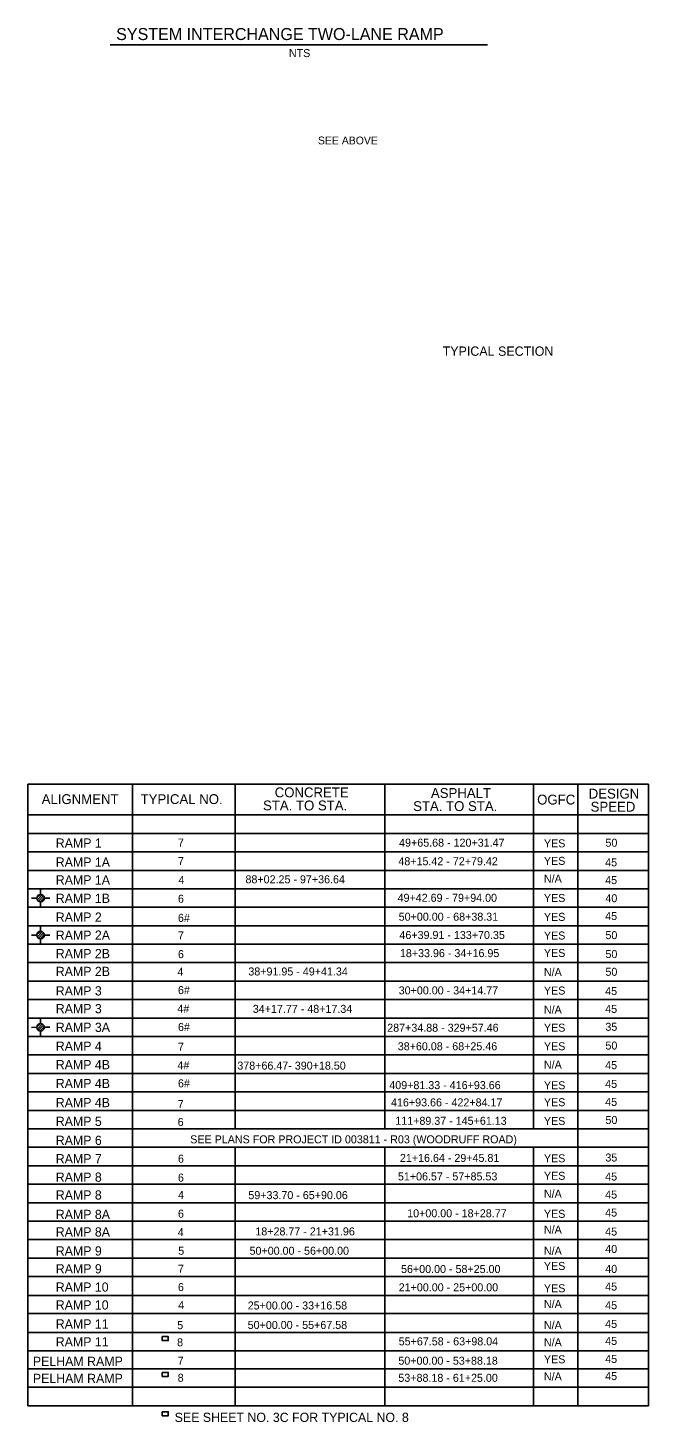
# Model space of a CAD drawing. Extents: x 4649 to 5578, y 4853 to 5383.
# Drawn here: x 5252.3 to 5345.4, y 4852.5 to 5061.7 of the extents above; entities that cross this region are included whole.
import ezdxf

# ---------------------------------------------------------------- set-up
doc = ezdxf.new("R2010")
doc.units = 0
for name, color, linetype in [('Level 1', 7, 'Continuous'), ('Level 3', 7, 'Continuous'), ('RD_EX_SU_Pole', 7, 'Continuous'), ('RD_Sketch10', 7, 'Continuous'), ('RD_TX_TypSect', 7, 'Continuous'), ('RD_XS_TieSlope', 7, 'Continuous')]:
    doc.layers.add(name, color=color, linetype=linetype)

# ---------------------------------------------------------------- blocks, each defined once
blk = doc.blocks.new('SUE_TFP')
at = {"layer": 'RD_EX_SU_Pole'}
for p, q in [((-2.21, 0.13), (-0.13, 2.21)), ((-1.96, -1.03), (1.03, 1.96)), ((-1.31, -1.79), (1.79, 1.31)), ((-0.3, -2.2), (2.2, 0.3)), ((0, 5.5), (0, 2.22)), ((2.22, 0), (5.53, 0.01)), ((-5.53, -0.01), (-2.22, 0)), ((0, -2.22), (0, -5.5))]:
    blk.add_line(p, q, dxfattribs=at)
blk.add_circle((0, 0), 2.22, dxfattribs=at)

msp = doc.modelspace()

# ---------------------------------------------------------------- linework, layer by layer
at = {"layer": 'Level 1'}
for p, q in [((5252.33, 4948.21), (5345.33, 4948.21)), ((5252.33, 4948.21), (5252.33, 4943.6)), ((5268.02, 4948.21), (5268.02, 4943.6)), ((5283.37, 4948.21), (5283.37, 4943.6)), ((5305.8, 4948.21), (5305.8, 4943.6)), ((5328.08, 4948.21), (5328.08, 4943.6)), ((5334.74, 4948.21), (5334.74, 4943.6)), ((5345.33, 4948.21), (5345.33, 4948.21)), ((5345.33, 4948.21), (5345.33, 4943.6)), ((5252.33, 4943.6), (5345.33, 4943.6)), ((5283.37, 4943.6), (5283.37, 4896.53)), ((5305.8, 4943.6), (5305.8, 4896.53)), ((5328.08, 4943.6), (5328.08, 4896.53)), ((5334.74, 4943.6), (5334.74, 4854.99)), ((5283.37, 4893.76), (5283.37, 4854.99)), ((5305.8, 4893.76), (5305.8, 4854.99)), ((5328.08, 4893.76), (5328.08, 4854.99))]:
    msp.add_line(p, q, dxfattribs=at)
at = {"layer": 'RD_TX_TypSect'}
for p, q in [((5264.65, 5059.12), (5321.2, 5059.12)), ((5252.33, 4943.6), (5252.33, 4854.99)), ((5268.02, 4943.6), (5268.02, 4854.99)), ((5345.33, 4943.6), (5345.33, 4854.99)), ((5252.33, 4940.83), (5345.33, 4940.83)), ((5252.33, 4938.06), (5345.33, 4938.06)), ((5252.33, 4935.29), (5345.33, 4935.29)), ((5252.33, 4932.52), (5345.33, 4932.52)), ((5252.33, 4929.75), (5345.33, 4929.75)), ((5252.33, 4926.99), (5345.33, 4926.99)), ((5252.33, 4924.22), (5345.33, 4924.22)), ((5252.33, 4921.45), (5345.33, 4921.45)), ((5252.33, 4918.68), (5345.33, 4918.68)), ((5252.33, 4915.91), (5345.33, 4915.91)), ((5252.33, 4913.14), (5345.33, 4913.14)), ((5252.33, 4910.37), (5345.33, 4910.37)), ((5252.33, 4907.6), (5345.33, 4907.6)), ((5252.33, 4904.83), (5345.33, 4904.83)), ((5252.33, 4902.06), (5345.33, 4902.06)), ((5252.33, 4899.3), (5345.33, 4899.3)), ((5252.33, 4896.53), (5345.33, 4896.53)), ((5252.33, 4893.76), (5345.33, 4893.76)), ((5252.33, 4890.99), (5345.33, 4890.99)), ((5252.33, 4888.22), (5345.33, 4888.22)), ((5252.33, 4885.45), (5345.33, 4885.45)), ((5252.33, 4882.68), (5345.33, 4882.68)), ((5252.33, 4879.91), (5345.33, 4879.91)), ((5252.33, 4877.14), (5345.33, 4877.14)), ((5252.33, 4874.37), (5345.33, 4874.37)), ((5252.33, 4871.54), (5345.33, 4871.54)), ((5252.33, 4868.84), (5345.33, 4868.84)), ((5252.41, 4865.98), (5345.41, 4865.98)), ((5252.33, 4863.24), (5345.33, 4863.24)), ((5252.33, 4860.53), (5345.33, 4860.53)), ((5252.33, 4857.76), (5345.33, 4857.76)), ((5252.33, 4854.99), (5345.33, 4854.99))]:
    msp.add_line(p, q, dxfattribs=at)
for points in [[(5272.45, 4865.36), (5273.35, 4865.36), (5273.35, 4864.76), (5272.45, 4864.76)], [(5272.45, 4859.99), (5273.35, 4859.99), (5273.35, 4859.39), (5272.45, 4859.39)], [(5272.45, 4854.08), (5273.35, 4854.08), (5273.35, 4853.48), (5272.45, 4853.48)]]:
    msp.add_lwpolyline(points, close=True, dxfattribs=at)

# ---------------------------------------------------------------- block references
at = {"layer": 'Level 3', "xscale": 0.24999999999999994, "yscale": 0.24999999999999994}
for p in [(5254.23, 4931.13), (5254.23, 4925.59), (5254.23, 4911.75)]:
    msp.add_blockref('SUE_TFP', p, dxfattribs=at)

# ---------------------------------------------------------------- texts
at = {"layer": 'RD_Sketch10'}
msp.add_text('TYPICAL SECTION', height=1.3967, dxfattribs=at).set_placement((5314.47, 5012.47))
at = {"layer": 'RD_TX_TypSect'}
for s, height, p in [('SYSTEM INTERCHANGE TWO-LANE RAMP', 1.8, (5265.55, 5059.83)), ('NTS', 1.2, (5291.44, 5057.27)), ('CONCRETE', 1.477, (5289.31, 4946.25)), ('ALIGNMENT', 1.477, (5254.39, 4945.24)), ('TYPICAL NO.', 1.4768, (5269.22, 4945.24)), ('STA. TO STA.', 1.4768, (5287.56, 4944.29)), ('STA. TO STA.', 1.4768, (5310.05, 4944.19)), ('ASPHALT', 1.477, (5312.72, 4946.15)), ('OGFC', 1.477, (5328.64, 4945.17)), ('DESIGN', 1.477, (5336.36, 4946.06)), ('SPEED', 1.477, (5336.65, 4944.1)), ('RAMP 1', 1.384, (5256.5, 4938.7)), ('7', 1.2, (5274.81, 4938.86)), ('49+65.68 - 120+31.47', 1.2, (5307.95, 4938.85)), ('YES', 1.2, (5329.65, 4938.74)), ('50', 1.2, (5338.87, 4938.84)), ('7', 1.2, (5274.81, 4936.09)), ('48+15.42 - 72+79.42', 1.2, (5307.84, 4936.06)), ('YES', 1.2, (5329.65, 4936.12)), ('RAMP 1A', 1.384, (5256.5, 4935.84)), ('45', 1.2, (5338.83, 4935.9)), ('RAMP 1A', 1.384, (5256.5, 4933.17)), ('4', 1.2, (5274.89, 4933.27)), ('88+02.25 - 97+36.64', 1.2, (5284.93, 4933.35)), ('N/A', 1.2, (5329.65, 4933.44)), ('45', 1.2, (5338.83, 4933.23)), ('RAMP 1B', 1.384, (5256.5, 4930.41)), ('6', 1.2, (5274.81, 4930.44)), ('49+42.69 - 79+94.00', 1.2, (5307.72, 4930.58)), ('YES', 1.2, (5329.65, 4930.55)), ('40', 1.2, (5338.86, 4930.52)), ('RAMP 2', 1.384, (5256.5, 4927.59)), ('50+00.00 - 68+38.31', 1.2, (5307.89, 4927.74)), ('YES', 1.2, (5329.65, 4927.72)), ('45', 1.2, (5338.83, 4927.84)), ('6#', 1.2, (5274.81, 4927.57)), ('RAMP 2A', 1.384, (5256.5, 4924.88)), ('7', 1.2, (5274.81, 4924.94)), ('46+39.91 - 133+70.35', 1.2, (5308, 4925)), ('YES', 1.2, (5329.65, 4924.92)), ('50', 1.2, (5338.87, 4924.98)), ('RAMP 2B', 1.384, (5256.5, 4922.12)), ('6', 1.2, (5274.81, 4922.13)), ('18+33.96 - 34+16.95', 1.2, (5308.07, 4922.28)), ('YES', 1.2, (5329.65, 4922.31)), ('50', 1.2, (5338.87, 4922.14)), ('RAMP 2B', 1.384, (5256.5, 4919.44)), ('4', 1.2, (5274.73, 4919.48)), ('38+91.95 - 49+41.34', 1.2, (5285.36, 4919.53)), ('N/A', 1.2, (5329.65, 4919.44)), ('50', 1.2, (5338.87, 4919.48)), ('RAMP 3', 1.384, (5256.5, 4916.53)), ('6#', 1.2, (5274.81, 4916.73)), ('30+00.00 - 34+14.77', 1.2, (5307.89, 4916.69)), ('YES', 1.2, (5329.65, 4916.67)), ('45', 1.2, (5338.83, 4916.59)), ('RAMP 3', 1.384, (5256.5, 4913.86)), ('4#', 1.2, (5274.73, 4913.96)), ('34+17.77 - 48+17.34', 1.2, (5286.03, 4913.92)), ('N/A', 1.2, (5329.65, 4913.8)), ('45', 1.2, (5338.83, 4913.91)), ('RAMP 3A', 1.384, (5256.5, 4911.06)), ('6#', 1.2, (5274.81, 4911.2)), ('287+34.88 - 329+57.46', 1.2, (5306.17, 4911.09)), ('YES', 1.2, (5329.65, 4911.1)), ('35', 1.2, (5338.86, 4911.23)), ('RAMP 4', 1.384, (5256.5, 4908.24)), ('7', 1.2, (5274.81, 4908.23)), ('38+60.08 - 68+25.46', 1.2, (5307.75, 4908.31)), ('YES', 1.2, (5329.65, 4908.31)), ('50', 1.2, (5338.87, 4908.42)), ('RAMP 4B', 1.384, (5256.5, 4905.46)), ('4#', 1.2, (5274.73, 4905.46)), ('378+66.47- 390+18.50', 1.2, (5283.71, 4905.41)), ('N/A', 1.2, (5329.65, 4905.55)), ('45', 1.2, (5338.83, 4905.48)), ('RAMP 4B', 1.384, (5256.5, 4902.64)), ('6#', 1.2, (5274.81, 4902.75)), ('45', 1.2, (5338.83, 4902.67)), ('409+81.33 - 416+93.66', 1.2, (5306.48, 4902.48)), ('YES', 1.2, (5329.65, 4902.46)), ('RAMP 4B', 1.384, (5256.5, 4899.77)), ('7', 1.2, (5274.77, 4899.63)), ('416+93.66 - 422+84.17', 1.2, (5306.74, 4899.89)), ('YES', 1.2, (5329.65, 4899.92)), ('45', 1.2, (5338.83, 4899.97)), ('RAMP 5', 1.384, (5256.5, 4896.96)), ('6', 1.2, (5274.77, 4896.95)), ('111+89.37 - 145+61.13', 1.2, (5307.38, 4897.13)), ('YES', 1.2, (5329.65, 4897.1)), ('50', 1.2, (5338.87, 4897.25)), ('RAMP 6', 1.384, (5256.5, 4894.11)), ('SEE PLANS FOR PROJECT ID 003811 - R03 (WOODRUFF ROAD)', 1.2, (5276.65, 4894.35)), ('RAMP 7', 1.384, (5256.5, 4891.35)), ('6', 1.2, (5274.81, 4891.45)), ('21+16.64 - 29+45.81', 1.2, (5308.07, 4891.56)), ('YES', 1.2, (5329.65, 4891.5)), ('35', 1.2, (5338.86, 4891.62)), ('RAMP 8', 1.384, (5256.5, 4888.59)), ('6', 1.2, (5274.81, 4888.61)), ('51+06.57 - 57+85.53', 1.2, (5307.77, 4888.79)), ('YES', 1.2, (5329.65, 4888.88)), ('45', 1.2, (5338.83, 4888.77)), ('RAMP 8', 1.384, (5256.5, 4885.91)), ('4', 1.2, (5274.82, 4886.01)), ('59+33.70 - 65+90.06', 1.2, (5285.36, 4885.98)), ('N/A', 1.2, (5329.65, 4886.19)), ('45', 1.2, (5338.83, 4886.07)), ('RAMP 8A', 1.384, (5256.5, 4883)), ('6', 1.2, (5274.81, 4883.2)), ('10+00.00 - 18+28.77', 1.2, (5309.16, 4883.26)), ('YES', 1.2, (5329.65, 4883.18)), ('45', 1.2, (5338.83, 4883.37)), ('RAMP 8A', 1.384, (5256.5, 4880.37)), ('4', 1.2, (5274.78, 4880.43)), ('18+28.77 - 21+31.96', 1.2, (5286.41, 4880.54)), ('N/A', 1.2, (5329.65, 4880.82)), ('45', 1.2, (5338.83, 4880.52)), ('RAMP 9', 1.384, (5256.5, 4877.52)), ('5', 1.2, (5274.85, 4877.64)), ('50+00.00 - 56+00.00', 1.2, (5285.54, 4877.64)), ('N/A', 1.2, (5329.65, 4877.64)), ('40', 1.2, (5338.84, 4877.91)), ('RAMP 9', 1.384, (5256.5, 4874.84)), ('7', 1.2, (5274.81, 4874.94)), ('56+00.00 - 58+25.00', 1.2, (5308.24, 4874.9)), ('YES', 1.2, (5329.65, 4875.36)), ('40', 1.2, (5338.84, 4874.92)), ('RAMP 10', 1.384, (5256.5, 4872.1)), ('6', 1.2, (5274.81, 4872.19)), ('21+00.00 - 25+00.00', 1.2, (5307.89, 4872.15)), ('YES', 1.2, (5329.65, 4872.01)), ('45', 1.2, (5338.83, 4872.27)), ('RAMP 10', 1.384, (5256.5, 4869.42)), ('4', 1.2, (5274.85, 4869.5)), ('25+00.00 - 33+16.58', 1.2, (5285.26, 4869.43)), ('N/A', 1.2, (5329.65, 4869.65)), ('45', 1.2, (5338.83, 4869.47)), ('RAMP 11', 1.384, (5256.5, 4866.57)), ('5', 1.2, (5274.71, 4866.48)), ('50+00.00 - 55+67.58', 1.2, (5285.26, 4866.51)), ('N/A', 1.2, (5329.65, 4866.49)), ('45', 1.2, (5338.83, 4866.67)), ('RAMP 11', 1.384, (5256.5, 4863.89)), ('8', 1.2, (5274.68, 4863.91)), ('55+67.58 - 63+98.04', 1.2, (5307.89, 4864.05)), ('N/A', 1.2, (5329.65, 4863.92)), ('45', 1.2, (5338.83, 4864.12)), ('PELHAM RAMP', 1.3845, (5253.07, 4860.96)), ('7', 1.2, (5274.77, 4861.15)), ('50+00.00 - 53+88.18', 1.2, (5307.84, 4861.15)), ('YES', 1.2, (5329.65, 4861.36)), ('45', 1.2, (5338.83, 4861.41)), ('N/A', 1.2, (5329.65, 4858.79)), ('45', 1.2, (5338.83, 4858.84)), ('PELHAM RAMP', 1.3845, (5253.07, 4858.4)), ('8', 1.2, (5274.77, 4858.59)), ('53+88.18 - 61+25.00', 1.2, (5307.84, 4858.58)), ('SEE SHEET NO. 3C FOR TYPICAL NO. 8', 1.3845, (5274.32, 4852.56))]:
    msp.add_text(s, height=height, dxfattribs=at).set_placement(p)
at = {"layer": 'RD_XS_TieSlope'}
msp.add_text('SEE ABOVE', height=1.173, dxfattribs=at).set_placement((5295.79, 5044.18))

doc.saveas('drawing.dxf')
